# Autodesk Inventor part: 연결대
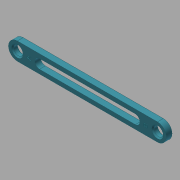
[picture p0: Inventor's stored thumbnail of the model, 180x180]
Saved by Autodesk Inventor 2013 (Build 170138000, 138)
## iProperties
Created: 2017-07
Part Number: 연결대
Material: 스테인리스강
Document SubType Name: Modeling
Designer: mduedu
Density: 8.08 g/cm^3
Mass: 46.8495 g
Surface Area: 49.3916 cm^2
Volume: 5.7982 cm^3
Author: mduedu
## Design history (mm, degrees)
sketch "스케치1"
  geometry: L1 (-67.5, 0)-(67.5, 0); L2 (-67.5, -7.5)-(67.5, -7.5); L3 (67.5, -7.5)-(67.5, 7.5); L4 (67.5, 7.5)-(-67.5, 7.5); L5 (-67.5, 7.5)-(-67.5, -7.5); L6 (-67.5, -7.5)-(67.5, 7.5); L7 (67.5, -7.5)-(-67.5, 7.5); 2 further points
  constraints: 14 end point, 4 midpoint, 2 horizontal, 2 parallel, 1 coincident, 1 perpendicular
  dimensions: "d0" = 135 distance of L1.start L1.end; "d2" = 15 distance of L2.end L3.end
extrude "돌출1" new body sketch "스케치1" distance "d3" = 5; taper "d4" = 0 deg
fillet "모깎기1"
fillet "모깎기2"
sketch "스케치2"
  geometry: C1 r 4 at (60, 0); A1 r 7.5 centre (60, 0) between (60, -7.5) and (60, 7.5) reference; 1 further point
  constraints: 1 centre point, 1 coincident
  dimensions: "d5" = 8 diameter of C1
extrude "돌출2" cut sketch "스케치2" stored distance "d6" = 10; taper "d7" = 0 deg
chamfer "모따기1" distance "d8" = 1; stored, may be unused: second distance "d9" = 2, angle "d10" = 45 deg
sketch "스케치3"
  geometry: L1 (-45, 0)-(45, 0); L2 (-45, -4)-(45, -4); L3 (45, -4)-(45, 4); L4 (45, 4)-(-45, 4); L5 (-45, 4)-(-45, -4); L6 (-45, -4)-(45, 4); L7 (45, -4)-(-45, 4); 2 further points
  constraints: 14 end point, 4 midpoint, 2 horizontal, 2 parallel, 1 coincident, 1 perpendicular
  dimensions: "d11" = 90 distance of L1.start L1.end; "d13" = 8 distance of L2.end L3.end
extrude "돌출3" cut sketch "스케치3" stored distance "d14" = 10; taper "d15" = 0 deg
fillet "모깎기3"
fillet "모깎기4"
sketch "스케치4"
  geometry: L1 (-60, 0)-(60, 0); C1 r 5 at (-60, 0) reference; C2 r 5 at (60, 0) reference; 3 further points
  constraints: 2 end point, 2 point on line, 1 horizontal, 2 other
  dimensions: "d16" = 50 distance of point (-50, 0) point (0, 0); "d17" = 50 distance of point (50, 0) point (0, 0)
feature "엠보싱1" sketch "스케치4" dims "d0" = 135, "d2" = 15, "d18" = 0.5, "d19" = 0
node "솔리드1"
mirror "대칭1"
